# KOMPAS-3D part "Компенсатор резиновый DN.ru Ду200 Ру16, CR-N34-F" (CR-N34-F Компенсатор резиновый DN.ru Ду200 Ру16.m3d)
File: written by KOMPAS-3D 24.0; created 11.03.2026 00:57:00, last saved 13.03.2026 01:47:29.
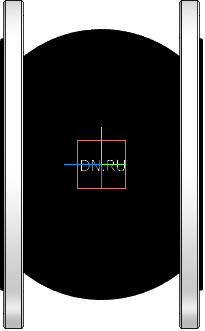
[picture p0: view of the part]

Document properties: Автор: DN.RU; Полное имя файла: CR-N34-F Компенсатор резиновый DN.ru Ду200 Ру16.cdw

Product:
- Body: Твердое тело2  | qty 1
    Масса: 46.753709
- Part/product: Компенсатор резиновый DN.ru Ду200 Ру16  | designation CR-N34-F
    Масса: 20
    Раздел спецификации: Прочие изделия
    Форматы листов документа: A2
    Комментарий: D140--02107
    Примечание: D140-02107
    additional columns: Типовые

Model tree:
1. Твердое тело2  (labels: Твердое тело2)

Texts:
  CR-N34-F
